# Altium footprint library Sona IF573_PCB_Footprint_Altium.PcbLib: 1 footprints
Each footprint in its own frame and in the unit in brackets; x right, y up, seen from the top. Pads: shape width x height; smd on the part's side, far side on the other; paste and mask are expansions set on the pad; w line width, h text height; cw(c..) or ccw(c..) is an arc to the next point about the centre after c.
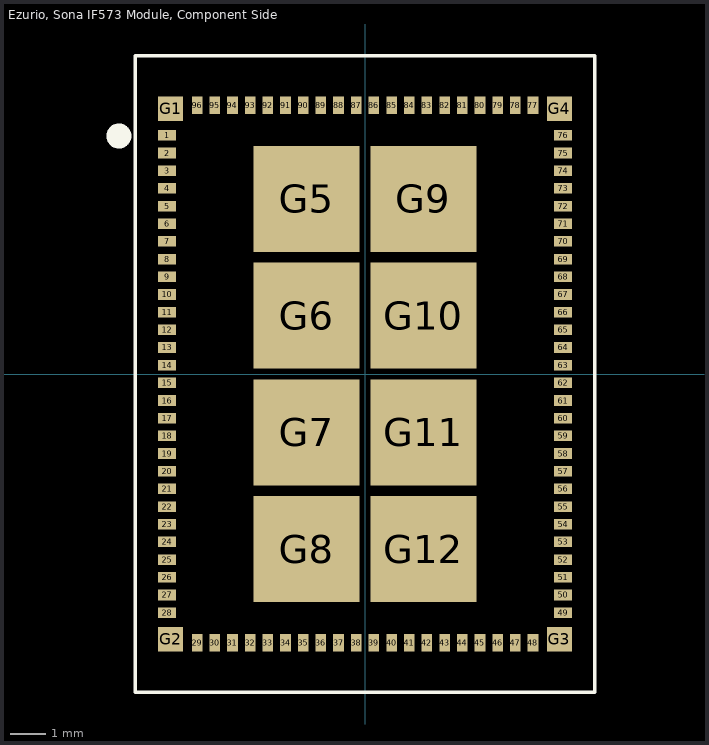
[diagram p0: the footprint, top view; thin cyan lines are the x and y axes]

## Ezurio, Sona IF573 Module, Component Side [mm] "Ezurio, Sona IF573 Module, Component Side"
height 1.9
pads (108):
  rect 0.5x0.3 smd mask+0.051: 1(-5.6,6.75) 2(-5.6,6.25) 3(-5.6,5.75) 4(-5.6,5.25) 5(-5.6,4.75) 6(-5.6,4.25) 7(-5.6,3.75) 8(-5.6,3.25) 9(-5.6,2.75) 10(-5.6,2.25) 11(-5.6,1.75) 12(-5.6,1.25) 13(-5.6,0.75) 14(-5.6,0.25) 15(-5.6,-0.25) 16(-5.6,-0.75) 17(-5.6,-1.25) 18(-5.6,-1.75) 19(-5.6,-2.25) 20(-5.6,-2.75) 21(-5.6,-3.25) 22(-5.6,-3.75) 23(-5.6,-4.25) 24(-5.6,-4.75) 25(-5.6,-5.25) 26(-5.6,-5.75) 27(-5.6,-6.25) 28(-5.6,-6.75) 49(5.6,-6.75) 50(5.6,-6.25) 51(5.6,-5.75) 52(5.6,-5.25) 53(5.6,-4.75) 54(5.6,-4.25) 55(5.6,-3.75) 56(5.6,-3.25) 57(5.6,-2.75) 58(5.6,-2.25) 59(5.6,-1.75) 60(5.6,-1.25) 61(5.6,-0.75) 62(5.6,-0.25) 63(5.6,0.25) 64(5.6,0.75) 65(5.6,1.25) 66(5.6,1.75) 67(5.6,2.25) 68(5.6,2.75) 69(5.6,3.25) 70(5.6,3.75) 71(5.6,4.25) 72(5.6,4.75) 73(5.6,5.25) 74(5.6,5.75) 75(5.6,6.25) 76(5.6,6.75)
  rect 0.3x0.5 smd mask+0.051: 29(-4.75,-7.6) 30(-4.25,-7.6) 31(-3.75,-7.6) 32(-3.25,-7.6) 33(-2.75,-7.6) 34(-2.25,-7.6) 35(-1.75,-7.6) 36(-1.25,-7.6) 37(-0.75,-7.6) 38(-0.25,-7.6) 39(0.25,-7.6) 40(0.75,-7.6) 41(1.25,-7.6) 42(1.75,-7.6) 43(2.25,-7.6) 44(2.75,-7.6) 45(3.25,-7.6) 46(3.75,-7.6) 47(4.25,-7.6) 48(4.75,-7.6) 77(4.75,7.6) 78(4.25,7.6) 79(3.75,7.6) 80(3.25,7.6) 81(2.75,7.6) 82(2.25,7.6) 83(1.75,7.6) 84(1.25,7.6) 85(0.75,7.6) 86(0.25,7.6) 87(-0.25,7.6) 88(-0.75,7.6) 89(-1.25,7.6) 90(-1.75,7.6) 91(-2.25,7.6) 92(-2.75,7.6) 93(-3.25,7.6) 94(-3.75,7.6) 95(-4.25,7.6) 96(-4.75,7.6)
  rect 0.7x0.7 smd mask+0.051: G1(-5.5,7.5) G2(-5.5,-7.5) G3(5.5,-7.5) G4(5.5,7.5)
  rect 3x3 smd mask+0.051: G5(-1.65,4.95) G6(-1.65,1.65) G7(-1.65,-1.65) G8(-1.65,-4.95) G9(1.65,4.95) G10(1.65,1.65) G11(1.65,-1.65) G12(1.65,-4.95)
Top Overlay:
  circle w0.381: c-6.963,6.732 r0.163
  lines w0.102: -6.5,-9 6.5,-9 6.5,9 -6.5,9 -6.5,-9
Mechanical 13:
  lines w0.025: -6.5,-9 -6.5,9 6.5,9 6.5,-9 -6.5,-9
3D body: height 0.01, standoff 0, extent 4.6,7.35 4.9,7.85
3D body: height 0.01, standoff 0, extent 4.1,7.35 4.4,7.85
3D body: height 0.01, standoff 0, extent 3.6,7.35 3.9,7.85
3D body: height 0.01, standoff 0, extent 3.1,7.35 3.4,7.85
3D body: height 0.01, standoff 0, extent 2.6,7.35 2.9,7.85
3D body: height 0.01, standoff 0, extent 2.1,7.35 2.4,7.85
3D body: height 0.01, standoff 0, extent 1.6,7.35 1.9,7.85
3D body: height 0.01, standoff 0, extent 1.1,7.35 1.4,7.85
3D body: height 0.01, standoff 0, extent 0.6,7.35 0.9,7.85
3D body: height 0.01, standoff 0, extent 0.1,7.35 0.4,7.85
3D body: height 0.01, standoff 0, extent -0.4,7.35 -0.1,7.85
3D body: height 0.01, standoff 0, extent -0.9,7.35 -0.6,7.85
3D body: height 0.01, standoff 0, extent -1.4,7.35 -1.1,7.85
3D body: height 0.01, standoff 0, extent -1.9,7.35 -1.6,7.85
3D body: height 0.01, standoff 0, extent -2.4,7.35 -2.1,7.85
3D body: height 0.01, standoff 0, extent -2.9,7.35 -2.6,7.85
3D body: height 0.01, standoff 0, extent -3.4,7.35 -3.1,7.85
3D body: height 0.01, standoff 0, extent -3.9,7.35 -3.6,7.85
3D body: height 0.01, standoff 0, extent -4.4,7.35 -4.1,7.85
3D body: height 0.01, standoff 0, extent -4.9,7.35 -4.6,7.85
3D body: height 0.01, standoff 0, extent -5.85,5.6 -5.35,5.9
3D body: height 0.01, standoff 0, extent -5.85,5.1 -5.35,5.4
3D body: height 0.01, standoff 0, extent -5.85,4.6 -5.35,4.9
3D body: height 0.01, standoff 0, extent -5.85,4.1 -5.35,4.4
3D body: height 0.01, standoff 0, extent -5.85,3.6 -5.35,3.9
3D body: height 0.01, standoff 0, extent -5.85,3.1 -5.35,3.4
3D body: height 0.01, standoff 0, extent -5.85,2.6 -5.35,2.9
3D body: height 0.01, standoff 0, extent -5.85,2.1 -5.35,2.4
3D body: height 0.01, standoff 0, extent -5.85,1.6 -5.35,1.9
3D body: height 0.01, standoff 0, extent -5.85,1.1 -5.35,1.4
3D body: height 0.01, standoff 0, extent -5.85,0.6 -5.35,0.9
3D body: height 0.01, standoff 0, extent -5.85,0.1 -5.35,0.4
3D body: height 0.01, standoff 0, extent -5.85,-0.4 -5.35,-0.1
3D body: height 0.01, standoff 0, extent -5.85,-0.9 -5.35,-0.6
3D body: height 0.01, standoff 0, extent -5.85,-1.4 -5.35,-1.1
3D body: height 0.01, standoff 0, extent -5.85,-1.9 -5.35,-1.6
3D body: height 0.01, standoff 0, extent -5.85,-2.4 -5.35,-2.1
3D body: height 0.01, standoff 0, extent -5.85,-2.9 -5.35,-2.6
3D body: height 0.01, standoff 0, extent -5.85,-3.4 -5.35,-3.1
3D body: height 0.01, standoff 0, extent -5.85,-3.9 -5.35,-3.6
3D body: height 0.01, standoff 0, extent -5.85,-4.4 -5.35,-4.1
3D body: height 0.01, standoff 0, extent -5.85,-4.9 -5.35,-4.6
3D body: height 0.01, standoff 0, extent 5.15,-7.85 5.85,-7.15
3D body: height 0.01, standoff 0, extent -5.85,-7.85 -5.15,-7.15
3D body: height 0.01, standoff 0, extent -5.85,7.15 -5.15,7.85
3D body: height 0.01, standoff 0, extent 5.15,7.15 5.85,7.85
3D body: height 0.01, standoff 0, extent -3.15,3.45 -0.15,6.45
3D body: height 0.01, standoff 0, extent 0.15,3.45 3.15,6.45
3D body: height 0.01, standoff 0, extent 0.15,0.15 3.15,3.15
3D body: height 0.01, standoff 0, extent -3.15,0.15 -0.15,3.15
3D body: height 0.01, standoff 0, extent -3.15,-3.15 -0.15,-0.15
3D body: height 0.01, standoff 0, extent 0.15,-3.15 3.15,-0.15
3D body: height 0.01, standoff 0, extent 0.15,-6.45 3.15,-3.45
3D body: height 0.01, standoff 0, extent -3.15,-6.45 -0.15,-3.45
3D body: height 0.01, standoff 0, extent -5.85,6.1 -5.35,6.4
3D body: height 0.01, standoff 0, extent -5.85,6.6 -5.35,6.9
3D body: height 0.01, standoff 0, extent -5.85,-5.4 -5.35,-5.1
3D body: height 0.01, standoff 0, extent -5.85,-5.9 -5.35,-5.6
3D body: height 0.01, standoff 0, extent -5.85,-6.4 -5.35,-6.1
3D body: height 0.01, standoff 0, extent -5.85,-6.9 -5.35,-6.6
3D body: height 0.01, standoff 0, extent -4.899,-7.85 -4.599,-7.35
3D body: height 0.01, standoff 0, extent -4.399,-7.85 -4.099,-7.35
3D body: height 0.01, standoff 0, extent -3.899,-7.85 -3.599,-7.35
3D body: height 0.01, standoff 0, extent -3.399,-7.85 -3.099,-7.35
3D body: height 0.01, standoff 0, extent -2.899,-7.85 -2.599,-7.35
3D body: height 0.01, standoff 0, extent -2.399,-7.85 -2.099,-7.35
3D body: height 0.01, standoff 0, extent -1.899,-7.85 -1.599,-7.35
3D body: height 0.01, standoff 0, extent -1.399,-7.85 -1.099,-7.35
3D body: height 0.01, standoff 0, extent -0.899,-7.85 -0.599,-7.35
3D body: height 0.01, standoff 0, extent -0.399,-7.85 -0.099,-7.35
3D body: height 0.01, standoff 0, extent 0.101,-7.85 0.401,-7.35
3D body: height 0.01, standoff 0, extent 0.601,-7.85 0.901,-7.35
3D body: height 0.01, standoff 0, extent 1.101,-7.85 1.401,-7.35
3D body: height 0.01, standoff 0, extent 1.601,-7.85 1.901,-7.35
3D body: height 0.01, standoff 0, extent 2.101,-7.85 2.401,-7.35
3D body: height 0.01, standoff 0, extent 2.601,-7.85 2.901,-7.35
3D body: height 0.01, standoff 0, extent 3.101,-7.85 3.401,-7.35
3D body: height 0.01, standoff 0, extent 3.601,-7.85 3.901,-7.35
3D body: height 0.01, standoff 0, extent 4.101,-7.85 4.401,-7.35
3D body: height 0.01, standoff 0, extent 4.6,-7.85 4.9,-7.35
3D body: height 0.01, standoff 0, extent 5.35,-6.899 5.85,-6.599
3D body: height 0.01, standoff 0, extent 5.35,-6.399 5.85,-6.099
3D body: height 0.01, standoff 0, extent 5.35,-5.899 5.85,-5.599
3D body: height 0.01, standoff 0, extent 5.35,-5.399 5.85,-5.099
3D body: height 0.01, standoff 0, extent 5.35,-4.899 5.85,-4.599
3D body: height 0.01, standoff 0, extent 5.35,-4.399 5.85,-4.099
3D body: height 0.01, standoff 0, extent 5.35,-3.899 5.85,-3.599
3D body: height 0.01, standoff 0, extent 5.35,-3.399 5.85,-3.099
3D body: height 0.01, standoff 0, extent 5.35,-2.899 5.85,-2.599
3D body: height 0.01, standoff 0, extent 5.35,-2.399 5.85,-2.099
3D body: height 0.01, standoff 0, extent 5.35,-1.899 5.85,-1.599
3D body: height 0.01, standoff 0, extent 5.35,-1.399 5.85,-1.099
3D body: height 0.01, standoff 0, extent 5.35,-0.899 5.85,-0.599
3D body: height 0.01, standoff 0, extent 5.35,-0.399 5.85,-0.099
3D body: height 0.01, standoff 0, extent 5.35,0.101 5.85,0.401
3D body: height 0.01, standoff 0, extent 5.35,0.601 5.85,0.901
3D body: height 0.01, standoff 0, extent 5.35,1.101 5.85,1.401
3D body: height 0.01, standoff 0, extent 5.35,1.601 5.85,1.901
3D body: height 0.01, standoff 0, extent 5.35,2.101 5.85,2.401
3D body: height 0.01, standoff 0, extent 5.35,2.601 5.85,2.901
3D body: height 0.01, standoff 0, extent 5.35,3.101 5.85,3.401
3D body: height 0.01, standoff 0, extent 5.35,3.601 5.85,3.901
3D body: height 0.01, standoff 0, extent 5.35,4.101 5.85,4.401
3D body: height 0.01, standoff 0, extent 5.35,4.601 5.85,4.901
3D body: height 0.01, standoff 0, extent 5.35,5.101 5.85,5.401
3D body: height 0.01, standoff 0, extent 5.35,5.601 5.85,5.901
3D body: height 0.01, standoff 0, extent 5.35,6.101 5.85,6.401
3D body: height 0.01, standoff 0, extent 5.35,6.6 5.85,6.9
